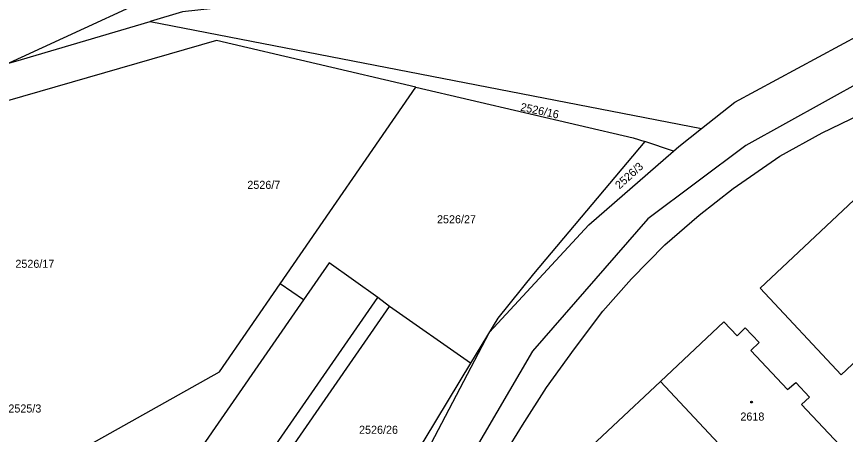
# Model space of a CAD drawing. Extents: x -527335 to -526256, y -1079142 to -1077836.
# Drawn here: x -527153 to -526978, y -1078442 to -1078353.8 of the extents above; entities that cross this region are included whole.
import ezdxf

# ---------------------------------------------------------------- set-up
doc = ezdxf.new("R2010")
doc.units = 0
for name, color, linetype in [('Hranice parcel', 7, 'Continuous'), ('Parcelní čísla', 7, 'Continuous'), ('Vnitřní kresba', 7, 'Continuous'), ('Vrstva 54', 7, 'Continuous'), ('Značky budov', 7, 'Continuous')]:
    doc.layers.add(name, color=color, linetype=linetype)

msp = doc.modelspace()

# ---------------------------------------------------------------- linework, layer by layer
at = {"layer": 'Hranice parcel'}
for p, q in [((-527124.8, -1078354.88), (-527008.42, -1078377.49)), ((-527097.36, -1078410.28), (-527068.7, -1078368.72)), ((-527014.31, -1078382.24), (-527020.38, -1078380.22)), ((-527092.4, -1078413.63), (-527097.36, -1078410.28)), ((-527074.28, -1078415.06), (-527076.74, -1078413.16)), ((-527057.14, -1078427.02), (-527074.28, -1078415.06)), ((-527017.02, -1078430.86), (-526997.96, -1078451.19))]:
    msp.add_line(p, q, dxfattribs=at)
for points in [[(-527045.51, -1078325.18), (-527044.42, -1078328.61), (-527072.01, -1078347.8), (-527117.91, -1078352.84), (-527124.8, -1078354.88)], [(-527008.42, -1078377.49), (-527001.38, -1078371.92), (-526974.73, -1078357.59), (-526955.89, -1078351.06), (-526922.67, -1078344.37), (-526902.66, -1078344.75), (-526884.52, -1078346.04), (-526843.79, -1078358.29), (-526811.67, -1078375.09)], [(-527115.65, -1078345.65), (-527152.02, -1078362.49), (-527154.6, -1078363.69)], [(-527154.6, -1078363.69), (-527151.91, -1078362.89), (-527124.8, -1078354.88)], [(-526758.4, -1078472.62), (-526766.27, -1078446.58), (-526780.95, -1078423.56), (-526794.44, -1078407.43), (-526800.43, -1078400.96), (-526814.56, -1078388.75), (-526829.06, -1078378.91), (-526860.51, -1078363.6), (-526886.41, -1078357.78), (-526924.51, -1078355.89), (-526949.93, -1078359.99), (-526973.92, -1078367.12), (-526999.06, -1078381.03), (-527019.7, -1078396.51), (-527044.07, -1078424.46), (-527066.65, -1078463.1), (-527068.91, -1078470.58)], [(-527068.7, -1078368.72), (-527110.78, -1078358.92), (-527154.86, -1078371.64)], [(-527068.7, -1078368.72), (-527022.78, -1078379.42), (-527020.38, -1078380.22)], [(-527014.31, -1078382.24), (-527013.19, -1078381.27), (-527008.42, -1078377.49)], [(-527020.38, -1078380.22), (-527043.88, -1078408.12), (-527051.36, -1078417.47), (-527057.14, -1078427.02)], [(-527073.97, -1078460.17), (-527053.17, -1078420.48), (-527032.18, -1078397.77), (-527014.31, -1078382.24)], [(-526996.03, -1078411.18), (-526969.26, -1078386.03), (-526952.12, -1078404.3), (-526978.92, -1078429.44), (-526996.03, -1078411.18)], [(-527076.74, -1078413.16), (-527087.02, -1078405.85), (-527092.4, -1078413.63)], [(-527141.86, -1078446.59), (-527110.16, -1078428.84), (-527097.36, -1078410.28)], [(-527092.4, -1078413.63), (-527138.83, -1078480.75), (-527128.47, -1078487.92), (-527076.74, -1078413.16)], [(-527079.86, -1078464.22), (-527080.96, -1078466.02), (-527100.14, -1078452.45), (-527074.28, -1078415.06)], [(-527017.02, -1078430.86), (-527003.64, -1078418.3), (-527000.89, -1078421.23), (-526999.14, -1078419.57), (-526996.24, -1078422.65), (-526998, -1078424.3), (-526990.24, -1078432.57), (-526988.5, -1078431.05), (-526985.62, -1078434.17), (-526987.27, -1078435.73), (-526979.26, -1078444.26), (-526992.65, -1078456.85), (-526997.96, -1078451.19)], [(-527057.14, -1078427.02), (-527066.8, -1078442.97), (-527076.81, -1078459.26)], [(-527025.9, -1078461.78), (-527037.31, -1078449.81), (-527037.19, -1078449.7), (-527017.02, -1078430.86)]]:
    msp.add_lwpolyline(points, dxfattribs=at)
at = {"layer": 'Vnitřní kresba'}
for p, q in [((-526982.92, -1078378.41), (-526974.87, -1078374.53)), ((-526991.83, -1078383.32), (-526982.92, -1078378.41)), ((-527001.73, -1078390.14), (-526991.83, -1078383.32)), ((-527008.85, -1078395.75), (-527001.73, -1078390.14)), ((-527016.12, -1078402.05), (-527008.85, -1078395.75)), ((-527023.2, -1078409.18), (-527016.12, -1078402.05)), ((-527029.21, -1078416.04), (-527023.2, -1078409.18)), ((-527035.2, -1078423.96), (-527029.21, -1078416.04)), ((-527041.08, -1078432.15), (-527035.2, -1078423.96)), ((-527046.19, -1078440.05), (-527041.08, -1078432.15)), ((-527051.06, -1078447.97), (-527046.19, -1078440.05))]:
    msp.add_line(p, q, dxfattribs=at)
at = {"layer": 'Vrstva 54'}
for points in [[(-527073.97, -1078460.17), (-527053.17, -1078420.48), (-527032.18, -1078397.77), (-527014.31, -1078382.24), (-527013.19, -1078381.27), (-527008.42, -1078377.49), (-527001.38, -1078371.92), (-526974.73, -1078357.59), (-526955.89, -1078351.06), (-526922.67, -1078344.37), (-526902.66, -1078344.75), (-526884.52, -1078346.04), (-526843.79, -1078358.29), (-526811.67, -1078375.09), (-526792.46, -1078391.93), (-526770.17, -1078411.49), (-526749.3, -1078465.23)], [(-526766.27, -1078446.58), (-526780.95, -1078423.56), (-526794.44, -1078407.43), (-526800.43, -1078400.96), (-526814.56, -1078388.75), (-526829.06, -1078378.91), (-526829.06, -1078378.91), (-526860.51, -1078363.6), (-526886.41, -1078357.78), (-526924.51, -1078355.89), (-526949.93, -1078359.99), (-526973.92, -1078367.12), (-526999.06, -1078381.03), (-527019.7, -1078396.51), (-527044.07, -1078424.46), (-527066.65, -1078463.1)]]:
    msp.add_lwpolyline(points, dxfattribs=at)
at = {"layer": 'Značky budov'}
msp.add_circle((-526997.83, -1078435.21), 0.175, dxfattribs=at)

# ---------------------------------------------------------------- texts
at = {"layer": 'Parcelní čísla'}
for s, rotation, p in [('2526/16', 348, (-527046.73, -1078373.68)), ('2526/3', 42, (-527025.69, -1078390.36))]:
    msp.add_text(s, height=1.7, rotation=rotation, dxfattribs=at).set_placement(p)
for s, p in [('2526/7', (-527104.26, -1078390.21)), ('2526/27', (-527064.22, -1078397.47)), ('2526/17', (-527153.22, -1078406.87)), ('2525/3', (-527154.7, -1078437.41)), ('2618', (-527000.18, -1078439.11)), ('2526/26', (-527080.68, -1078441.9))]:
    msp.add_text(s, height=1.7, dxfattribs=at).set_placement(p)

doc.saveas('drawing.dxf')
